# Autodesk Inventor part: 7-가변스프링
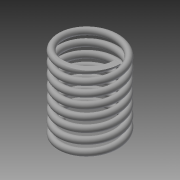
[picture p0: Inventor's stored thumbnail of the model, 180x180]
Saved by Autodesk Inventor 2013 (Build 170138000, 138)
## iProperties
Created: 2014-12
Part Number: 7-가변스프링
Material: 일반
Document SubType Name: Modeling
Designer: cad10
Density: 1 g/cm^3
Author: cad10
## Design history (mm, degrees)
sketch "스케치1"
  geometry: L1 (0, 0)-(17.5, 0); L2 (17.5, 0)-(17.5, 48.5); L3 (17.5, 48.5)-(0, 48.5); L4 (0, 48.5)-(0, 0); C1 r 2 at (17.5, 0)
  constraints: 8 end point, 2 parallel, 1 centre point, 1 coincident, 1 horizontal, 1 perpendicular
  dimensions: "d0" = 4 diameter of C1; "d2" = 48.5 distance between parallel lines of L1 L3 (derived); "d3" = 35 diameter of L2 L4
feature "코일1" sketch "스케치1" pitch "d4" = 10; turns "d6" = 7.5; dims "d5" = 48.5 (= d2), "d7" = 0, angle "d8" = 90 deg, angle "d9" = 90 deg, "d10" = 0, "d11" = 0
sketch "스케치2"
  geometry: L1 (-19.5, 0)-(-15.5, 0) reference; 1 further point
  constraints: 1 horizontal alignment
extrude "돌출1" cut sketch "스케치2" distance "d12" = 10; taper "d13" = 0 deg
node "작업 평면1"
sketch "스케치3"
  geometry: L1 (15.5, 0)-(19.5, 0) reference; 1 further point
  constraints: 1 horizontal alignment
extrude "돌출2" cut sketch "스케치3" stored distance "d14" = 10; taper "d15" = 0 deg
node "솔리드1"
node "절단 모서리 투영1"
node "절단 모서리 투영2"
